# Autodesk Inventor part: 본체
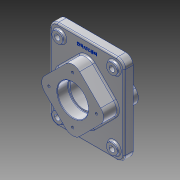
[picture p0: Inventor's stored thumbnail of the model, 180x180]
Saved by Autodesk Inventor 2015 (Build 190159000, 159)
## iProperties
Created: 2026-07
Part Number: 본체
Material: 알루미늄 6061
Document SubType Name: Modeling
Designer: USER
Density: 2.7 g/cm^3
Appearance: 알루미늄 - 평지
Mass: 2132.41 g
Surface Area: 955.114 cm^2
Volume: 789.782 cm^3
Author: USER
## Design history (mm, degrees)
sketch "스케치1"
  geometry: L1 (75, -90)-(-75, -90); L2 (-75, -90)-(-75, 90); L3 (-75, 90)-(75, 90); L4 (75, 90)-(75, -90); L5 (75, -90)-(-75, 90); L6 (-75, -90)-(75, 90); 1 further point
  constraints: 12 end point, 2 midpoint, 2 parallel, 1 horizontal, 1 perpendicular
  dimensions: "d0" = 150 distance of L2.end L3.end; "d1" = 180 distance of L1.end L2.end
extrude "돌출1" new body sketch "스케치1" distance "d2" = 18; taper "d3" = 0 deg
fillet "모깎기1" dims "d4" = 15
sketch "스케치5"
  geometry: L1 (0, 70.711)-(70.711, 0); L2 (70.711, 0)-(0, -70.711); L3 (0, -70.711)-(-70.711, 0); L4 (-70.711, 0)-(0, 70.711); 2 further points
  constraints: 8 end point, 1 coincident, 1 vertical alignment, 9 other
  dimensions: "d5" = 100 distance of L1.start L1.end
extrude "돌출2" join sketch "스케치5" distance "d6" = 29; taper "d7" = 0 deg
fillet "모깎기2" dims "d10" = 20
sketch "스케치8"
  geometry: L1 (0, -70.711)-(-70.711, 0); L2 (-70.711, 0)-(0, 70.711); L3 (0, 70.711)-(70.711, 0); L4 (70.711, 0)-(0, -70.711); 2 further points
  constraints: 8 end point, 1 coincident, 1 vertical alignment, 9 other
  dimensions: "d12" = 100 distance of L1.start L1.end
extrude "돌출3" join sketch "스케치8" distance "d13" = 23; taper "d14" = 0 deg
fillet "모깎기3" dims "d15" = 20
sketch "스케치10"
  geometry: L1 (-75, -75)-(-75, 75) reference; C1 r 11 at (-55, 70); 1 further point
  constraints: 1 centre point
  dimensions: "d16" = 22 diameter of C1; "d17" = 20 distance from line of C1.centre L1
extrude "돌출4" join sketch "스케치10" distance "d18" = 5; taper "d19" = 0 deg
hole "구멍1" diameter "d22" = 11; stored, may be unused: countersink angle "d26" = 90 deg, drill point angle "d28" = 0 deg; dims "d20" = 10, "d21" = 10, "d23" = 6, "d24" = 4, "d25" = 2, "d27" = 8.8
sketch "스케치12"
  geometry: L1 (60, 90)-(-60, 90) reference; 3 further points
  constraints: 1 midpoint, 1 vertical alignment, 1 other
  dimensions: "d37" = 15 distance from line of point (0, 75) L1
feature "엠보싱1" sketch "스케치12" dims "d0" = 150, "d1" = 180, "d38" = 0.5, "d39" = 0
sketch "스케치13"
  geometry: C1 r 31 at (0, 0); 1 further point
  constraints: 1 centre point, 1 coincident
  dimensions: "d40" = 62 diameter of C1
extrude "돌출5" cut sketch "스케치13" distance "d41" = 22; taper "d42" = 0 deg
hole "구멍2" diameter "d45" = 54; stored, may be unused: countersink angle "d49" = 90 deg, drill point angle "d51" = 0 deg; dims "d43" = 10, "d44" = 10, "d46" = 6, "d47" = 4, "d48" = 2, "d50" = 8.8
sketch "스케치14"
  geometry: C1 r 31 at (0, 0); 1 further point
  constraints: 1 centre point, 1 coincident
  dimensions: "d52" = 62 diameter of C1
extrude "돌출6" cut sketch "스케치14" distance "d53" = 22; taper "d54" = 0 deg
sketch "스케치15"
  geometry: L1 (0, 0)-(0, 48)
  constraints: 2 end point, 1 vertical
  dimensions: "d55" = 48 distance of L1.start L1.end
hole "구멍3" sketch "스케치15" at (0, 48) diameter "d56" = 4.917; stored, may be unused: countersink angle "d60" = 90 deg, drill point angle "d62" = 118 deg; dims "d57" = 10, "d58" = 4, "d59" = 2, "d61" = 13
sketch "스케치16"
  geometry: L1 (0, 0)-(0, -48)
  constraints: 2 end point, 1 vertical
  dimensions: "d66" = 48 distance of L1.start L1.end
hole "구멍4" sketch "스케치16" at (0, -48) diameter "d67" = 4.917; stored, may be unused: countersink angle "d71" = 90 deg, drill point angle "d73" = 118 deg; dims "d68" = 10, "d69" = 4, "d70" = 2, "d72" = 13
fillet "모깎기4" dims "d77" = 3
fillet "모깎기5" dims "d78" = 1
chamfer "모따기1" distance "d79" = 1; stored, may be unused: second distance "d80" = 2, angle "d81" = 45 deg
node "솔리드1"
pattern_linear "직사각형 패턴1"
pattern_circular "원형 패턴1" dims angle "d64" = 360 deg
pattern_circular "원형 패턴2" dims angle "d75" = 360 deg
